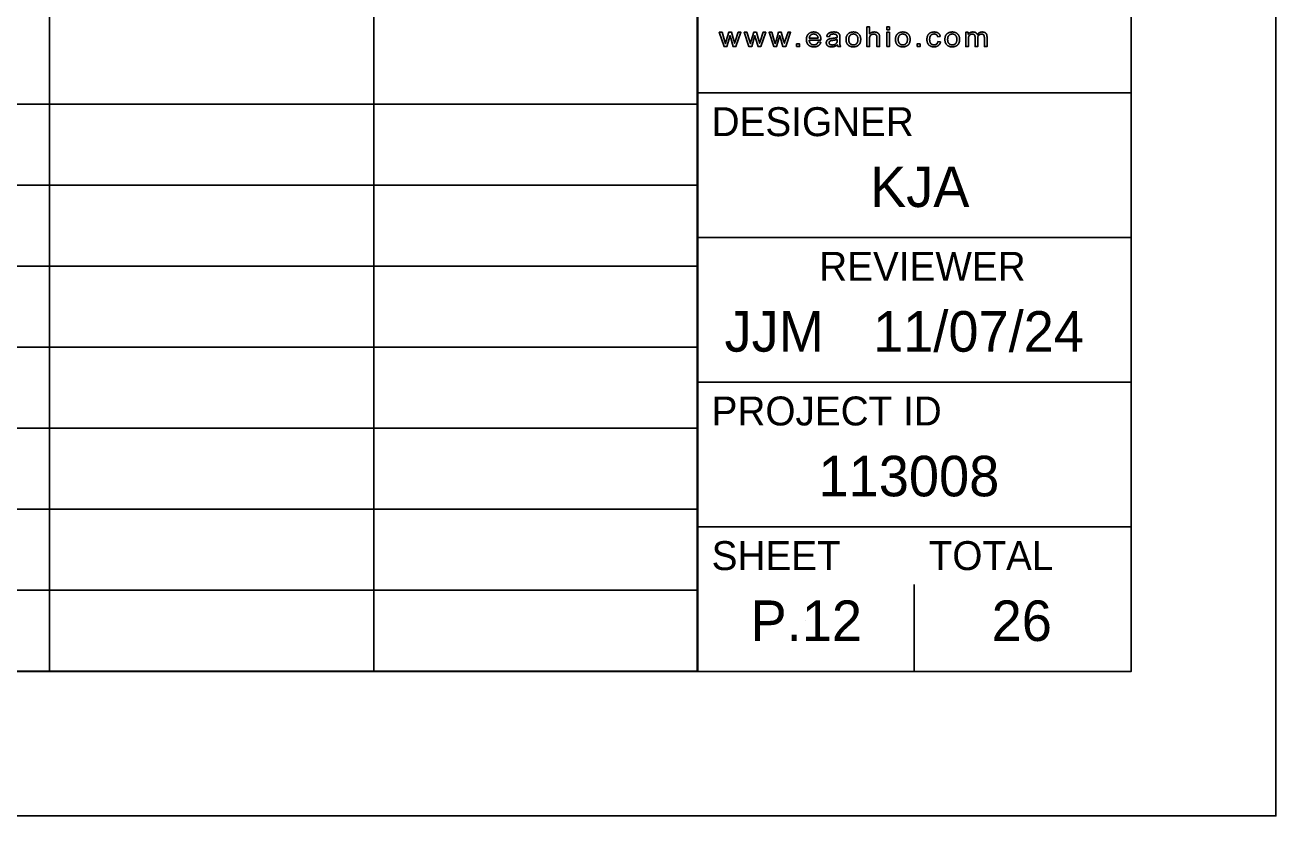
# Model space of a CAD drawing. Extents: x 0 to 34, y 0 to 22.
# Drawn here: x 29.678 to 34, y 0 to 2.734 of the extents above; entities that cross this region are included whole.
import ezdxf

# ---------------------------------------------------------------- set-up
doc = ezdxf.new("R2010")
doc.units = 0
for name, color, linetype in [('SH_Border', 7, 'Continuous'), ('SH_Cut_Line', 7, 'Continuous'), ('SH_Data', 7, 'Continuous'), ('SH_Text', 7, 'Continuous'), ('TX_X_20', 7, 'Continuous')]:
    doc.layers.add(name, color=color, linetype=linetype)

msp = doc.modelspace()

# ---------------------------------------------------------------- linework, layer by layer
at = {"layer": 'SH_Border'}
for p, q in [((32, 0.5), (32, 21.5)), ((32, 2.5), (33.5, 2.5)), ((32, 2), (33.5, 2)), ((32, 1.5), (33.5, 1.5)), ((32, 1), (33.5, 1))]:
    msp.add_line(p, q, dxfattribs=at)
msp.add_lwpolyline([(1.5, 21.5), (33.5, 21.5), (33.5, 0.5), (1.5, 0.5)], close=True, dxfattribs=at)
at = {"layer": 'SH_Cut_Line'}
msp.add_lwpolyline([(0, 0), (34, 0), (34, 22), (0, 22)], close=True, dxfattribs=at)
at = {"layer": 'SH_Data'}
for p, q in [((32.75, 0.5), (32.75, 0.8)), ((32.375, 0.675), (32.375, 0.675))]:
    msp.add_line(p, q, dxfattribs=at)
at = {"layer": 'SH_Text'}
for p, q in [((29.7625, 21.5), (29.7625, 0.5008)), ((30.8825, 21.5), (30.8825, 0.5008)), ((32.0024, 21.5), (32.0024, 0.5008)), ((1.5, 2.4607), (32.0024, 2.4607)), ((1.5, 2.1807), (32.0024, 2.1807)), ((1.5, 1.9007), (32.0024, 1.9007)), ((1.5, 1.6207), (32.0024, 1.6207)), ((1.5, 1.3407), (32.0024, 1.3407)), ((1.5, 1.0607), (32.0024, 1.0607)), ((1.5, 0.7807), (32.0024, 0.7807)), ((1.5, 0.5008), (32.0024, 0.5008))]:
    msp.add_line(p, q, dxfattribs=at)
at = {"layer": 'TX_X_20'}
for p, q in [((32.387, 2.6821), (32.4274, 2.6821)), ((32.4178, 2.6889), (32.3875, 2.6889)), ((32.4477, 2.6948), (32.4567, 2.6937)), ((32.4838, 2.6843), (32.4838, 2.6812)), ((32.4931, 2.6802), (32.4931, 2.6913)), ((32.5143, 2.6842), (32.5143, 2.6842)), ((32.5238, 2.6842), (32.5238, 2.6842)), ((32.6852, 2.6842), (32.6852, 2.6842)), ((32.6946, 2.6842), (32.6946, 2.6842)), ((32.8402, 2.6944), (32.8313, 2.6931)), ((32.856, 2.6842), (32.856, 2.6842)), ((32.8655, 2.6842), (32.8655, 2.6842)), ((32.4272, 2.6744), (32.4177, 2.6755)), ((32.4846, 2.6656), (32.4846, 2.6656)), ((32.4864, 2.6596), (32.496, 2.6596)), ((32.8321, 2.6776), (32.8411, 2.6765))]:
    msp.add_line(p, q, dxfattribs=at)
for points in [[(32.5955, 2.6865), (32.5955, 2.6596), (32.5863, 2.6596), (32.5863, 2.7276), (32.5955, 2.7276), (32.5955, 2.7032)], [(32.1007, 2.68), (32.1093, 2.7089), (32.1188, 2.7089), (32.1269, 2.6802), (32.1295, 2.6708), (32.1327, 2.6804), (32.142, 2.7089), (32.1509, 2.7089), (32.1339, 2.6596), (32.1244, 2.6596), (32.1158, 2.6891), (32.1137, 2.6975), (32.1027, 2.6596), (32.0931, 2.6596), (32.0766, 2.7089), (32.0861, 2.7089), (32.0947, 2.6804), (32.0979, 2.6698)], [(32.1867, 2.68), (32.1953, 2.7089), (32.2048, 2.7089), (32.2129, 2.6802), (32.2155, 2.6708), (32.2186, 2.6804), (32.228, 2.7089), (32.2369, 2.7089), (32.2199, 2.6596), (32.2104, 2.6596), (32.2018, 2.6891), (32.1997, 2.6975), (32.1886, 2.6596), (32.179, 2.6596), (32.1625, 2.7089), (32.172, 2.7089), (32.1807, 2.6804), (32.1838, 2.6698)], [(32.2726, 2.68), (32.2813, 2.7089), (32.2907, 2.7089), (32.2988, 2.6802), (32.3015, 2.6708), (32.3046, 2.6804), (32.3139, 2.7089), (32.3229, 2.7089), (32.3059, 2.6596), (32.2964, 2.6596), (32.2878, 2.6891), (32.2856, 2.6975), (32.2746, 2.6596), (32.265, 2.6596), (32.2485, 2.7089), (32.258, 2.7089), (32.2666, 2.6804), (32.2698, 2.6698)], [(32.6305, 2.6908), (32.6305, 2.6596), (32.6213, 2.6596), (32.6213, 2.6908)], [(32.9372, 2.6851), (32.9372, 2.6596), (32.928, 2.6596), (32.928, 2.7089), (32.9362, 2.7089), (32.9362, 2.7019)], [(32.9694, 2.6882), (32.9694, 2.6596), (32.9602, 2.6596), (32.9602, 2.6916)], [(33.0015, 2.6934), (33.0015, 2.6596), (32.9923, 2.6596), (32.9923, 2.6906)]]:
    msp.add_lwpolyline(points, dxfattribs=at)
for points in [[(32.655, 2.718), (32.6642, 2.718), (32.6642, 2.7276), (32.655, 2.7276)], [(32.655, 2.6596), (32.6642, 2.6596), (32.6642, 2.7089), (32.655, 2.7089)], [(32.3437, 2.6596), (32.3437, 2.669), (32.3541, 2.669), (32.3541, 2.6596)], [(32.7597, 2.6596), (32.7597, 2.669), (32.7702, 2.669), (32.7702, 2.6596)]]:
    msp.add_lwpolyline(points, close=True, dxfattribs=at)
for points in [[(32.0979, 2.6698), (32.0981, 2.6706), (32.1007, 2.68)], [(32.1838, 2.6698), (32.184, 2.6706), (32.1867, 2.68)], [(32.2698, 2.6698), (32.27, 2.6706), (32.2726, 2.68)], [(32.3846, 2.7031), (32.3775, 2.6962), (32.3775, 2.6838)], [(32.3775, 2.6838), (32.3775, 2.6718), (32.3845, 2.6651)], [(32.4028, 2.71), (32.3916, 2.71), (32.3846, 2.7031)], [(32.3921, 2.6696), (32.3875, 2.6739), (32.387, 2.6821)], [(32.3875, 2.6889), (32.388, 2.6954), (32.3923, 2.6992)], [(32.3923, 2.6992), (32.3966, 2.7031), (32.4029, 2.7031)], [(32.4206, 2.7032), (32.4137, 2.71), (32.4028, 2.71)], [(32.4029, 2.7031), (32.4099, 2.7031), (32.4143, 2.6983)], [(32.4143, 2.6983), (32.4172, 2.6951), (32.4178, 2.6889)], [(32.4275, 2.6843), (32.4275, 2.6965), (32.4206, 2.7032)], [(32.4274, 2.6821), (32.4275, 2.6835), (32.4275, 2.6843)], [(32.4517, 2.7032), (32.4489, 2.7), (32.4477, 2.6948)], [(32.4526, 2.684), (32.4497, 2.6822), (32.4479, 2.6792)], [(32.4598, 2.7082), (32.4545, 2.7065), (32.4517, 2.7032)], [(32.4592, 2.6867), (32.4555, 2.6858), (32.4526, 2.684)], [(32.4567, 2.6937), (32.4581, 2.6989), (32.4612, 2.701)], [(32.4674, 2.688), (32.4619, 2.6873), (32.4592, 2.6867)], [(32.4721, 2.71), (32.4651, 2.71), (32.4598, 2.7082)], [(32.4608, 2.6795), (32.4631, 2.6804), (32.4688, 2.6811)], [(32.4612, 2.701), (32.4643, 2.7031), (32.4708, 2.7031)], [(32.4838, 2.6908), (32.4785, 2.6892), (32.4674, 2.688)], [(32.4688, 2.6811), (32.4788, 2.6824), (32.4838, 2.6843)], [(32.4708, 2.7031), (32.4777, 2.7031), (32.4812, 2.7002)], [(32.4834, 2.7085), (32.479, 2.71), (32.4721, 2.71)], [(32.4812, 2.7002), (32.4838, 2.6981), (32.4838, 2.693)], [(32.4838, 2.6812), (32.4838, 2.6757), (32.4823, 2.6729)], [(32.4897, 2.7047), (32.4877, 2.707), (32.4834, 2.7085)], [(32.4838, 2.693), (32.4838, 2.6925), (32.4838, 2.6908)], [(32.4926, 2.699), (32.4918, 2.7025), (32.4897, 2.7047)], [(32.4931, 2.6913), (32.4931, 2.6969), (32.4926, 2.699)], [(32.4936, 2.6655), (32.4931, 2.6686), (32.4931, 2.6802)], [(32.5227, 2.7045), (32.5143, 2.6979), (32.5143, 2.6842)], [(32.5143, 2.6842), (32.5143, 2.6717), (32.5214, 2.6651)], [(32.5398, 2.71), (32.5297, 2.71), (32.5227, 2.7045)], [(32.5238, 2.6842), (32.5238, 2.6937), (32.5283, 2.6984)], [(32.5283, 2.67), (32.5238, 2.6747), (32.5238, 2.6842)], [(32.5283, 2.6984), (32.5329, 2.7031), (32.5398, 2.7031)], [(32.558, 2.7033), (32.5509, 2.71), (32.5398, 2.71)], [(32.5398, 2.7031), (32.5465, 2.7031), (32.5511, 2.6983)], [(32.5511, 2.6983), (32.5556, 2.6936), (32.5556, 2.6845)], [(32.5556, 2.6845), (32.5556, 2.6748), (32.5511, 2.6701)], [(32.5651, 2.6849), (32.5651, 2.6966), (32.558, 2.7033)], [(32.562, 2.67), (32.5651, 2.6754), (32.5651, 2.6849)], [(32.5955, 2.7032), (32.602, 2.71), (32.6118, 2.71)], [(32.5971, 2.6956), (32.5955, 2.6923), (32.5955, 2.6865)], [(32.6022, 2.7008), (32.5986, 2.6989), (32.5971, 2.6956)], [(32.6099, 2.7028), (32.6058, 2.7028), (32.6022, 2.7008)], [(32.6183, 2.6999), (32.6153, 2.7028), (32.6099, 2.7028)], [(32.6118, 2.71), (32.6178, 2.71), (32.6222, 2.7078)], [(32.6213, 2.6908), (32.6213, 2.697), (32.6183, 2.6999)], [(32.6222, 2.7078), (32.6267, 2.7056), (32.6286, 2.7018)], [(32.6286, 2.7018), (32.6305, 2.698), (32.6305, 2.6908)], [(32.6935, 2.7045), (32.6852, 2.6979), (32.6852, 2.6842)], [(32.6852, 2.6842), (32.6852, 2.6717), (32.6922, 2.6651)], [(32.7106, 2.71), (32.7005, 2.71), (32.6935, 2.7045)], [(32.6946, 2.6842), (32.6946, 2.6937), (32.6992, 2.6984)], [(32.6992, 2.67), (32.6946, 2.6747), (32.6946, 2.6842)], [(32.6992, 2.6984), (32.7037, 2.7031), (32.7106, 2.7031)], [(32.7288, 2.7033), (32.7218, 2.71), (32.7106, 2.71)], [(32.7106, 2.7031), (32.7174, 2.7031), (32.7219, 2.6983)], [(32.7219, 2.6983), (32.7265, 2.6936), (32.7265, 2.6845)], [(32.7265, 2.6845), (32.7265, 2.6748), (32.7219, 2.6701)], [(32.7359, 2.6849), (32.7359, 2.6966), (32.7288, 2.7033)], [(32.7328, 2.67), (32.7359, 2.6754), (32.7359, 2.6849)], [(32.7939, 2.684), (32.7939, 2.692), (32.7968, 2.698)], [(32.8006, 2.6651), (32.7939, 2.6717), (32.7939, 2.684)], [(32.7968, 2.698), (32.7997, 2.704), (32.8056, 2.707)], [(32.8077, 2.6986), (32.8033, 2.6941), (32.8033, 2.6843)], [(32.8033, 2.6843), (32.8033, 2.6743), (32.8075, 2.6698)], [(32.8056, 2.707), (32.8116, 2.71), (32.8186, 2.71)], [(32.8189, 2.7031), (32.812, 2.7031), (32.8077, 2.6986)], [(32.8186, 2.71), (32.8274, 2.71), (32.833, 2.7059)], [(32.8268, 2.7006), (32.8235, 2.7031), (32.8189, 2.7031)], [(32.8313, 2.6931), (32.83, 2.6981), (32.8268, 2.7006)], [(32.833, 2.7059), (32.8387, 2.7018), (32.8402, 2.6944)], [(32.8644, 2.7045), (32.856, 2.6979), (32.856, 2.6842)], [(32.856, 2.6842), (32.856, 2.6717), (32.863, 2.6651)], [(32.8814, 2.71), (32.8714, 2.71), (32.8644, 2.7045)], [(32.8655, 2.6842), (32.8655, 2.6937), (32.87, 2.6984)], [(32.87, 2.67), (32.8655, 2.6747), (32.8655, 2.6842)], [(32.87, 2.6984), (32.8745, 2.7031), (32.8814, 2.7031)], [(32.8997, 2.7033), (32.8926, 2.71), (32.8814, 2.71)], [(32.8814, 2.7031), (32.8882, 2.7031), (32.8927, 2.6983)], [(32.8927, 2.6983), (32.8973, 2.6936), (32.8973, 2.6845)], [(32.8973, 2.6845), (32.8973, 2.6748), (32.8928, 2.6701)], [(32.9068, 2.6849), (32.9068, 2.6966), (32.8997, 2.7033)], [(32.9036, 2.67), (32.9068, 2.6754), (32.9068, 2.6849)], [(32.9362, 2.7019), (32.9388, 2.7055), (32.943, 2.7077)], [(32.9387, 2.6954), (32.9372, 2.6918), (32.9372, 2.6851)], [(32.9434, 2.7008), (32.9401, 2.699), (32.9387, 2.6954)], [(32.943, 2.7077), (32.9472, 2.71), (32.9527, 2.71)], [(32.9506, 2.7027), (32.9467, 2.7027), (32.9434, 2.7008)], [(32.958, 2.6999), (32.9557, 2.7027), (32.9506, 2.7027)], [(32.9527, 2.71), (32.9587, 2.71), (32.9625, 2.7077)], [(32.9602, 2.6916), (32.9602, 2.6971), (32.958, 2.6999)], [(32.9625, 2.7077), (32.9664, 2.7054), (32.968, 2.7013)], [(32.968, 2.7013), (32.9744, 2.71), (32.9847, 2.71)], [(32.9732, 2.6992), (32.9694, 2.6958), (32.9694, 2.6882)], [(32.9827, 2.7027), (32.977, 2.7027), (32.9732, 2.6992)], [(32.9882, 2.7014), (32.9858, 2.7027), (32.9827, 2.7027)], [(32.9847, 2.71), (32.9928, 2.71), (32.9972, 2.7059)], [(32.9914, 2.6978), (32.9905, 2.7), (32.9882, 2.7014)], [(32.9923, 2.6906), (32.9923, 2.6956), (32.9914, 2.6978)], [(32.9972, 2.7059), (33.0015, 2.7018), (33.0015, 2.6934)], [(32.3845, 2.6651), (32.3915, 2.6585), (32.4034, 2.6585)], [(32.4034, 2.6653), (32.3966, 2.6653), (32.3921, 2.6696)], [(32.412, 2.6677), (32.4085, 2.6653), (32.4034, 2.6653)], [(32.4034, 2.6585), (32.4128, 2.6585), (32.4189, 2.6626)], [(32.4177, 2.6755), (32.4156, 2.6702), (32.412, 2.6677)], [(32.4189, 2.6626), (32.4249, 2.6668), (32.4272, 2.6744)], [(32.4479, 2.6792), (32.4461, 2.6762), (32.4461, 2.6726)], [(32.4461, 2.6726), (32.4461, 2.6664), (32.4509, 2.6624)], [(32.4509, 2.6624), (32.4556, 2.6585), (32.4646, 2.6585)], [(32.4559, 2.6728), (32.4559, 2.675), (32.4571, 2.6768)], [(32.4586, 2.6672), (32.4559, 2.6695), (32.4559, 2.6728)], [(32.4571, 2.6768), (32.4584, 2.6785), (32.4608, 2.6795)], [(32.4668, 2.665), (32.4614, 2.665), (32.4586, 2.6672)], [(32.4646, 2.6585), (32.47, 2.6585), (32.4747, 2.6601)], [(32.4762, 2.6671), (32.4721, 2.665), (32.4668, 2.665)], [(32.4747, 2.6601), (32.4794, 2.6617), (32.4846, 2.6656)], [(32.4823, 2.6729), (32.4803, 2.6692), (32.4762, 2.6671)], [(32.4846, 2.6656), (32.485, 2.6622), (32.4864, 2.6596)], [(32.496, 2.6596), (32.4942, 2.6624), (32.4936, 2.6655)], [(32.5214, 2.6651), (32.5284, 2.6585), (32.5398, 2.6585)], [(32.5398, 2.6653), (32.5329, 2.6653), (32.5283, 2.67)], [(32.5511, 2.6701), (32.5466, 2.6653), (32.5398, 2.6653)], [(32.5398, 2.6585), (32.5468, 2.6585), (32.5528, 2.6615)], [(32.5528, 2.6615), (32.5588, 2.6645), (32.562, 2.67)], [(32.6922, 2.6651), (32.6992, 2.6585), (32.7106, 2.6585)], [(32.7106, 2.6653), (32.7037, 2.6653), (32.6992, 2.67)], [(32.7219, 2.6701), (32.7174, 2.6653), (32.7106, 2.6653)], [(32.7106, 2.6585), (32.7177, 2.6585), (32.7237, 2.6615)], [(32.7237, 2.6615), (32.7297, 2.6645), (32.7328, 2.67)], [(32.8185, 2.6585), (32.8074, 2.6585), (32.8006, 2.6651)], [(32.8075, 2.6698), (32.8117, 2.6653), (32.8185, 2.6653)], [(32.8185, 2.6653), (32.8239, 2.6653), (32.8275, 2.6683)], [(32.8335, 2.6633), (32.8274, 2.6585), (32.8185, 2.6585)], [(32.8275, 2.6683), (32.8311, 2.6713), (32.8321, 2.6776)], [(32.8411, 2.6765), (32.8396, 2.668), (32.8335, 2.6633)], [(32.863, 2.6651), (32.87, 2.6585), (32.8814, 2.6585)], [(32.8814, 2.6653), (32.8745, 2.6653), (32.87, 2.67)], [(32.8928, 2.6701), (32.8882, 2.6653), (32.8814, 2.6653)], [(32.8814, 2.6585), (32.8885, 2.6585), (32.8945, 2.6615)], [(32.8945, 2.6615), (32.9005, 2.6645), (32.9036, 2.67)]]:
    msp.add_open_spline(points, degree=2, dxfattribs=at)

# ---------------------------------------------------------------- texts
at = {"layer": 'SH_Data'}
for s, height, p in [('DESIGNER', 0.1, (32.05, 2.35)), ('KJA', 0.14, (32.5975, 2.105)), ('REVIEWER', 0.1, (32.4218, 1.85)), ('JJM', 0.14, (32.0946, 1.605)), ('11/07/24', 0.14, (32.6078, 1.605)), ('PROJECT ID', 0.1, (32.05, 1.35)), ('113008', 0.14, (32.4193, 1.105)), ('SHEET', 0.1, (32.05, 0.85)), ('TOTAL', 0.1, (32.8, 0.85)), ('P.12', 0.14, (32.1845, 0.605)), ('26', 0.14, (33.0176, 0.605))]:
    msp.add_text(s, height=height, dxfattribs=at).set_placement(p)

doc.saveas('drawing.dxf')
